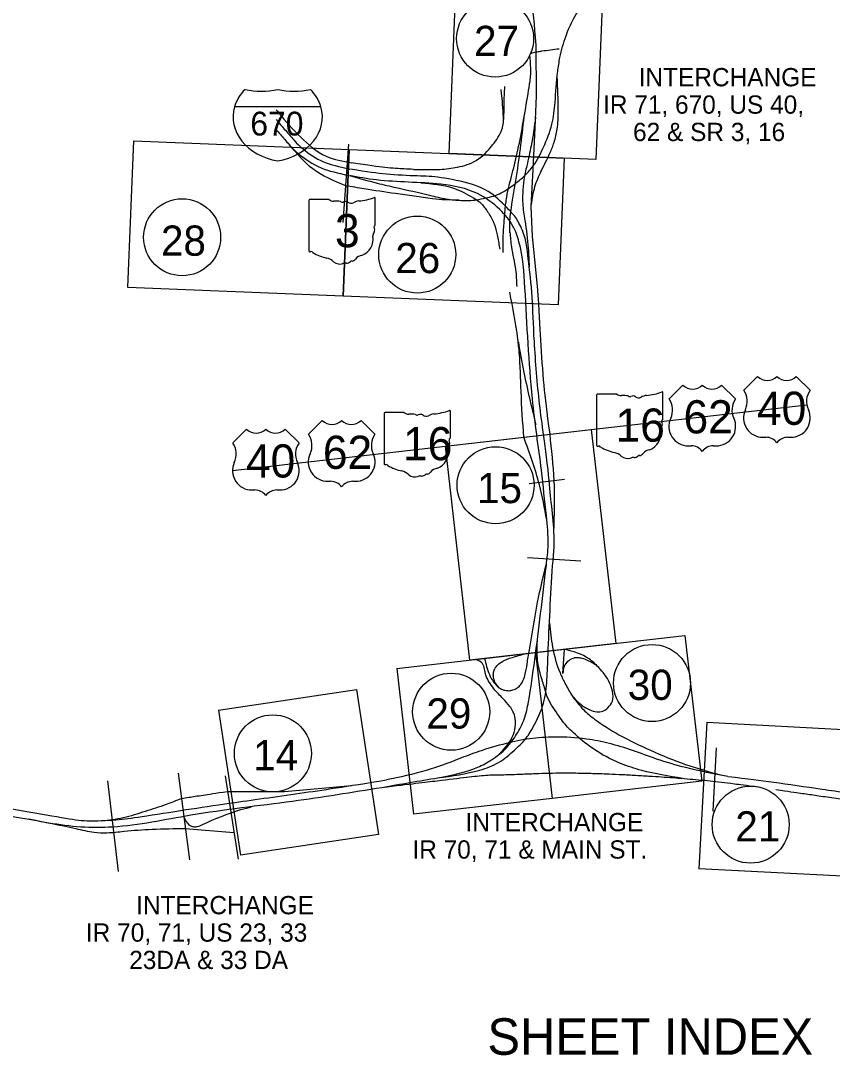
# Model space of a CAD drawing. Extents: x -13 to 322, y -402 to 112.
# Drawn here: x 3.22 to 7.61, y 67.48 to 73.08 of the extents above; entities that cross this region are included whole.
import ezdxf

# ---------------------------------------------------------------- set-up
doc = ezdxf.new("R2010")
doc.units = 0
for name, color, linetype in [('GM_X_Interstate_Shield', 7, 'Continuous'), ('GM_X_State_Shield', 7, 'Continuous'), ('GM_X_US_Shield', 7, 'Continuous'), ('SC_Scratch1', 7, 'Continuous'), ('SH_Data', 7, 'Continuous'), ('SH_Text', 7, 'Continuous')]:
    doc.layers.add(name, color=color, linetype=linetype)

msp = doc.modelspace()

# ---------------------------------------------------------------- linework, layer by layer
at = {"layer": 'GM_X_Interstate_Shield'}
msp.add_line((4.8438, 72.6183), (4.3763, 72.6183), dxfattribs=at)
msp.add_line((4.8438, 72.6183), (4.3763, 72.6183), dxfattribs=at)
for centre, start_param, end_param in [((4.6705, 72.5631), 2.47259, 2.911027), ((4.5218, 72.9442), 4.415841, 5.008937), ((4.6983, 72.9442), 4.415841, 5.008937), ((4.5496, 72.5631), 0.230566, 0.669003), ((4.6705, 72.5631), 2.911027, 4.511031), ((4.5496, 72.5631), 4.913747, 6.513751)]:
    msp.add_ellipse(centre, major_axis=(0.3022, 0), ratio=0.8, start_param=start_param, end_param=end_param, dxfattribs=at)
at = {"layer": 'GM_X_State_Shield'}
for p, q in [((4.7791, 72.1115), (4.7791, 71.8391)), ((4.8878, 72.1162), (4.7827, 72.1162)), ((5.1381, 71.9804), (5.1381, 72.1229)), ((5.1381, 71.9805), (5.1381, 71.9804)), ((6.3359, 71.059), (6.3359, 70.7865)), ((6.4445, 71.0637), (6.3394, 71.0637)), ((6.6948, 70.9279), (6.6948, 71.0704)), ((5.2942, 70.9635), (5.1891, 70.9635)), ((5.5445, 70.8277), (5.5445, 70.9702)), ((5.1855, 70.9588), (5.1855, 70.6863)), ((6.6948, 70.9279), (6.6948, 70.9279)), ((5.5445, 70.8277), (5.5445, 70.8277))]:
    msp.add_line(p, q, dxfattribs=at)
for centre, radius, start, end in [((4.7833, 72.1121), 0.00416, 98.1301, 188.1301), ((4.9128, 72.1478), 0.0403, 231.6195, 271.1119), ((4.9262, 71.9632), 0.1448, 80.4867, 94.9883), ((4.9591, 72.1135), 0.0116, 219.7921, 297.1024), ((4.9762, 72.082), 0.0242, 54.4667, 119.1411), ((5.0074, 72.1252), 0.0291, 233.8562, 294.8282), ((5.0588, 72.033), 0.0766, 97.3462, 120.7689), ((5.0102, 72.4876), 0.3807, 275.8445, 288.9065), ((5.1341, 72.1235), 0.004, 351.8621, 97.738), ((5.1372, 71.97), 0.00618, 107.944, 210.337), ((5.1338, 71.9799), 0.00428, 289.6038, 7.7341), ((5.0316, 71.9027), 0.0952, 292.3089, 8.9858), ((5.1524, 71.9208), 0.027, 136.8065, 186.9296), ((5.0978, 71.952), 0.0371, 340.033, 23.6496), ((4.7833, 71.8385), 0.0042, 171.9584, 258.3066), ((4.7839, 71.8663), 0.032, 267.339, 280.6039), ((4.7905, 71.8234), 0.0115, 29.7484, 93.2717), ((4.9362, 72.0681), 0.2749, 240.4129, 257.1985), ((4.8543, 71.7167), 0.086, 47.1842, 75.836), ((5.0717, 71.7626), 0.0521, 94.4031, 142.5768), ((4.9473, 71.822), 0.0546, 230.7004, 286.2918), ((4.9788, 71.7278), 0.0448, 85.6951, 111.2099), ((4.9828, 71.8016), 0.0291, 268.777, 315.5493), ((5.0091, 71.7752), 0.00819, 65.7517, 132.6484), ((5.0056, 71.8127), 0.0308, 282.8732, 323.2771), ((6.567, 71.4351), 0.3807, 275.8445, 288.9065), ((6.6909, 71.071), 0.004, 351.8621, 97.738), ((6.34, 71.0596), 0.00416, 98.1301, 188.1301), ((6.4696, 71.0953), 0.0403, 231.6195, 271.1119), ((6.4829, 70.9107), 0.1448, 80.4867, 94.9883), ((6.5158, 71.061), 0.0116, 219.7921, 297.1024), ((6.5329, 71.0295), 0.0242, 54.4667, 119.1411), ((6.5641, 71.0727), 0.0291, 233.8562, 294.8282), ((6.6155, 70.9805), 0.0766, 97.3462, 120.7689), ((5.1897, 70.9594), 0.00416, 98.1301, 188.1301), ((5.3192, 70.9951), 0.0403, 231.6195, 271.1119), ((5.4166, 71.3349), 0.3807, 275.8445, 288.9065), ((5.5405, 70.9708), 0.004, 351.8621, 97.738), ((5.3326, 70.8105), 0.1448, 80.4867, 94.9883), ((5.3655, 70.9608), 0.0116, 219.7921, 297.1024), ((5.3826, 70.9293), 0.0242, 54.4667, 119.1411), ((5.4138, 70.9725), 0.0291, 233.8562, 294.8282), ((5.4652, 70.8803), 0.0766, 97.3462, 120.7689), ((6.6939, 70.9174), 0.00618, 107.944, 210.337), ((6.6546, 70.8994), 0.0371, 340.033, 23.6496), ((6.6906, 70.9274), 0.00428, 289.6038, 7.7341), ((6.5883, 70.8501), 0.0952, 292.3089, 8.9858), ((6.7092, 70.8683), 0.027, 136.8065, 186.9296), ((5.5436, 70.8172), 0.00618, 107.944, 210.337), ((5.5042, 70.7992), 0.0371, 340.033, 23.6496), ((5.5402, 70.8271), 0.00428, 289.6038, 7.7341), ((5.438, 70.7499), 0.0952, 292.3089, 8.9858), ((5.5588, 70.7681), 0.027, 136.8065, 186.9296), ((6.34, 70.7859), 0.0042, 171.9584, 258.3066), ((6.3407, 70.8138), 0.032, 267.339, 280.6039), ((6.3472, 70.7708), 0.0115, 29.7484, 93.2717), ((6.493, 71.0156), 0.2749, 240.4129, 257.1985), ((6.411, 70.6641), 0.086, 47.1842, 75.836), ((6.5624, 70.7601), 0.0308, 282.8732, 323.2771), ((6.6284, 70.7101), 0.0521, 94.4031, 142.5768), ((5.1897, 70.6857), 0.0042, 171.9584, 258.3066), ((5.1903, 70.7136), 0.032, 267.339, 280.6039), ((5.1969, 70.6706), 0.0115, 29.7484, 93.2717), ((6.504, 70.7695), 0.0546, 230.7004, 286.2918), ((6.5356, 70.6753), 0.0448, 85.6951, 111.2099), ((6.5396, 70.7491), 0.0291, 268.777, 315.5493), ((6.5659, 70.7227), 0.00819, 65.7517, 132.6484), ((5.3426, 70.9154), 0.2749, 240.4129, 257.1985), ((5.2607, 70.5639), 0.086, 47.1842, 75.836), ((5.3537, 70.6693), 0.0546, 230.7004, 286.2918), ((5.3892, 70.6489), 0.0291, 268.777, 315.5493), ((5.4155, 70.6225), 0.00819, 65.7517, 132.6484), ((5.412, 70.6599), 0.0308, 282.8732, 323.2771), ((5.4781, 70.6098), 0.0521, 94.4031, 142.5768), ((5.3852, 70.5751), 0.0448, 85.6951, 111.2099)]:
    msp.add_arc(centre, radius, start, end, dxfattribs=at)
at = {"layer": 'GM_X_US_Shield'}
for p, q in [((7.2067, 71.1587), (7.1319, 71.0839)), ((7.4909, 71.0839), (7.4161, 71.1587)), ((6.803, 71.1124), (6.7282, 71.0376)), ((7.0871, 71.0376), (7.0124, 71.1124)), ((4.8514, 70.9204), (4.7766, 70.8457)), ((5.1356, 70.8457), (5.0608, 70.9204)), ((4.4412, 70.8734), (4.3664, 70.7987)), ((4.7253, 70.7987), (4.6506, 70.8734)), ((7.2366, 70.8296), (7.2516, 70.8296)), ((7.3712, 70.8296), (7.3862, 70.8296)), ((6.8329, 70.7834), (6.8478, 70.7834)), ((6.9675, 70.7834), (6.9824, 70.7834)), ((4.8813, 70.5914), (4.8963, 70.5914)), ((5.0159, 70.5914), (5.0309, 70.5914)), ((4.4711, 70.5444), (4.486, 70.5444)), ((4.6057, 70.5444), (4.6206, 70.5444))]:
    msp.add_line(p, q, dxfattribs=at)
for centre, radius, start, end in [((7.2591, 71.2121), 0.0748, 225.573, 314.427), ((7.3638, 71.2121), 0.0748, 225.573, 314.427), ((6.8553, 71.1658), 0.0748, 225.573, 314.427), ((6.96, 71.1658), 0.0748, 225.573, 314.427), ((7.0462, 71.0238), 0.1047, 334.5471, 35.0009), ((7.5766, 71.0238), 0.1047, 144.9991, 205.4529), ((6.6424, 70.9776), 0.1047, 334.5471, 35.0009), ((7.1729, 70.9776), 0.1047, 144.9991, 205.4529), ((7.2355, 70.9343), 0.1047, 154.8319, 270.6383), ((7.3874, 70.9343), 0.1047, 269.3617, 25.1681), ((4.9038, 70.9738), 0.0748, 225.573, 314.427), ((5.0085, 70.9738), 0.0748, 225.573, 314.427), ((6.8317, 70.8881), 0.1047, 154.8319, 270.6383), ((6.9836, 70.8881), 0.1047, 269.3617, 25.1681), ((4.4935, 70.9268), 0.0748, 225.573, 314.427), ((4.5982, 70.9268), 0.0748, 225.573, 314.427), ((4.2806, 70.7386), 0.1047, 334.5471, 35.0009), ((4.8111, 70.7386), 0.1047, 144.9991, 205.4529), ((4.6909, 70.7856), 0.1047, 334.5471, 35.0009), ((5.2213, 70.7856), 0.1047, 144.9991, 205.4529), ((7.2516, 70.7548), 0.0748, 36.8699, 90), ((7.3712, 70.7548), 0.0748, 90, 143.1301), ((4.8802, 70.6961), 0.1047, 154.8319, 270.6383), ((5.0321, 70.6961), 0.1047, 269.3617, 25.1681), ((6.8478, 70.7086), 0.0748, 36.8699, 90), ((6.9675, 70.7086), 0.0748, 90, 143.1301), ((4.4699, 70.6491), 0.1047, 154.8319, 270.6383), ((4.6218, 70.6491), 0.1047, 269.3617, 25.1681), ((4.8963, 70.5166), 0.0748, 36.8699, 90), ((5.0159, 70.5166), 0.0748, 90, 143.1301), ((4.486, 70.4696), 0.0748, 36.8699, 90), ((4.6057, 70.4696), 0.0748, 90, 143.1301)]:
    msp.add_arc(centre, radius, start, end, dxfattribs=at)
at = {"layer": 'SC_Scratch1'}
for p, q in [((4.9927, 72.4172), (4.9617, 71.9918)), ((5.9715, 70.5796), (6.1614, 70.6026)), ((5.962, 70.178), (6.2505, 70.1614)), ((6.9835, 69.1481), (6.9655, 68.8061)), ((4.0718, 69.0109), (4.1325, 68.5422)), ((3.6884, 68.9704), (3.746, 68.4786)), ((4.3255, 68.9978), (4.3956, 68.5458))]:
    msp.add_line(p, q, dxfattribs=at)
at = {"layer": 'SH_Data'}
for p, q in [((6.0114, 72.6785), (6.008, 72.9517)), ((6.0029, 72.5049), (6.0114, 72.6785)), ((5.9919, 72.2784), (6.0029, 72.5049)), ((5.9822, 72.0784), (5.9919, 72.2784)), ((5.9891, 71.9173), (5.9822, 72.0784)), ((6.0159, 71.6476), (5.9891, 71.9173)), ((4.3652, 70.6492), (7.4736, 71.0052)), ((5.6812, 69.6269), (6.1629, 69.682)), ((6.1531, 69.5515), (6.1629, 69.682)), ((4.6476, 68.9123), (5.0096, 68.9451)), ((4.3387, 68.9124), (4.6476, 68.9123)), ((4.1105, 68.7122), (4.3733, 68.6896))]:
    msp.add_line(p, q, dxfattribs=at)
for points in [[(6.008, 72.9517), (5.9996, 73.0713), (5.9862, 73.1903), (5.9331, 73.5852), (5.8824, 73.8595), (5.8496, 74.1336)], [(4.6013, 72.5504), (4.6147, 72.5344), (4.6283, 72.5185), (4.6877, 72.4504), (4.7345, 72.3955), (4.8585, 72.3096), (4.9386, 72.2972), (5.0003, 72.2815)], [(4.6013, 72.4959), (4.606, 72.4904), (4.6108, 72.4849), (4.6609, 72.4274), (4.7053, 72.3728), (4.8475, 72.2742), (4.9327, 72.2623), (4.9916, 72.2472)], [(5.3457, 72.2801), (5.3257, 72.281), (5.3059, 72.2818), (5.1937, 72.287), (5.1051, 72.3005), (5.0091, 72.3157)], [(6.073, 70.6552), (6.049, 70.8453), (6.0202, 71.0345), (5.9929, 71.4138), (5.9899, 71.6065), (5.9586, 71.8476), (5.9552, 71.8986), (5.9145, 71.9989), (5.8813, 72.0414), (5.7746, 72.1521), (5.6737, 72.2009), (5.478, 72.2413), (5.3801, 72.243), (5.1897, 72.2518), (5.0997, 72.2656), (5.0036, 72.2808)], [(6.0836, 70.846), (6.0668, 70.9734), (6.0509, 71.0999), (6.0319, 71.3634), (6.0271, 71.5075), (6.0159, 71.6476)], [(6.0966, 70.1345), (6.1062, 70.2154), (6.1091, 70.3124), (6.0892, 70.4835), (6.0821, 70.5683), (6.0731, 70.6544)], [(5.1737, 68.9343), (5.3294, 68.9531), (5.4851, 68.9719), (5.6408, 68.9907), (5.7364, 69.0022), (5.8329, 69.0026), (5.9291, 69.0063), (6.0036, 69.0091), (6.078, 69.0121), (6.1525, 69.0127), (6.1931, 69.0129), (6.2338, 69.0124), (6.2745, 69.0114), (6.3151, 69.0104), (6.3558, 69.0093), (6.3964, 69.0076), (6.4777, 69.0042), (6.559, 68.9997), (6.6403, 68.9946), (6.7022, 68.9907), (6.7641, 68.9861), (6.8259, 68.981), (6.8877, 68.9758), (6.9495, 68.9702), (7.0111, 68.9628), (7.0768, 68.9548), (7.1425, 68.9463), (7.2081, 68.9371)], [(2.1217, 68.7431), (2.1524, 68.7533), (2.1841, 68.7617), (2.3195, 68.7847), (2.4083, 68.7979), (2.5999, 68.8247), (2.6959, 68.8403), (2.9915, 68.8527), (3.1857, 68.8151), (3.4721, 68.767), (3.5635, 68.749), (3.7498, 68.7583), (3.8458, 68.7722), (4.1303, 68.8162), (4.3223, 68.8461), (4.7428, 68.9036), (4.9712, 68.9382), (5.1993, 68.9753)], [(7.0452, 68.9938), (7.1606, 68.9807), (7.2757, 68.9657), (7.5619, 68.9243), (7.7318, 68.8991), (7.903, 68.8824)], [(4.0894, 68.8749), (4.105, 68.8774), (4.1205, 68.8798), (4.2036, 68.8925), (4.2712, 68.9026), (4.3387, 68.9124)], [(7.3063, 68.9231), (7.3754, 68.9131), (7.4444, 68.9028), (7.5135, 68.8928), (7.6078, 68.8792), (7.7022, 68.8669), (7.7969, 68.857), (7.815, 68.8551), (7.8331, 68.8533), (7.8512, 68.8515)]]:
    msp.add_open_spline(points, degree=3, dxfattribs=at)
for points in [[(4.9981, 72.2459), (5.1483, 72.2055), (5.2518, 72.1811), (5.4323, 72.1404), (5.5235, 72.1195), (5.6034, 72.1121), (5.6861, 72.1153), (5.7355, 72.1253), (5.7778, 72.1357), (5.8594, 72.1765), (5.8968, 72.2042), (5.9464, 72.2456), (5.9929, 72.2989), (6.0481, 72.3994), (6.0943, 72.525), (6.1109, 72.6421), (6.1254, 72.809), (6.1376, 72.8857), (6.1702, 73.0026), (6.211, 73.0952), (6.2763, 73.1933), (6.3428, 73.2685), (6.3653, 73.2857), (6.4612, 73.3619), (6.542, 73.4064), (6.6444, 73.4447), (6.7391, 73.4623), (6.8117, 73.4683), (6.9653, 73.4683), (7.0726, 73.4713), (7.2097, 73.4784), (7.357, 73.494), (7.5219, 73.5113), (7.7497, 73.5556)], [(5.979, 72.908), (5.9941, 72.9119), (6.0093, 72.9154), (6.0322, 72.9197), (6.04, 72.9209), (6.0867, 72.9273), (6.1335, 72.9329)], [(5.8307, 71.8292), (5.8299, 71.9128), (5.8326, 71.9547), (5.8358, 71.9965), (5.8381, 72.0297), (5.8409, 72.0629), (5.8446, 72.096), (5.8495, 72.1289), (5.8631, 72.1933), (5.8791, 72.257), (5.8954, 72.3206), (5.91, 72.3846), (5.9389, 72.5362), (5.9651, 72.6888), (5.9757, 72.7581), (5.979, 72.7929), (5.9794, 72.8277), (5.9751, 72.8992)], [(5.9828, 72.0895), (6.0023, 72.1869), (6.0362, 72.2707), (6.0831, 72.367), (6.1058, 72.4252), (6.1226, 72.497), (6.1282, 72.5963), (6.1226, 72.7807)], [(5.3457, 72.2801), (5.4875, 72.2801), (5.5829, 72.2917), (5.6843, 72.3284), (5.7729, 72.4121), (5.823, 72.4964), (5.8344, 72.5725), (5.8387, 72.7194), (5.8395, 72.7293)], [(5.8322, 72.5483), (5.8228, 72.6802), (5.8193, 72.7129)], [(4.6013, 72.6031), (4.6152, 72.5858), (4.7329, 72.4554), (4.8727, 72.3505), (5.0091, 72.3157)], [(5.8667, 71.9364), (5.8669, 71.9987), (5.8716, 72.0497), (5.899, 72.22), (5.944, 72.5643)], [(6.0057, 72.5629), (5.9816, 72.4078), (5.9578, 72.2995), (5.9421, 72.2237), (5.936, 72.1509), (5.936, 72.0948), (5.9479, 72.0035), (5.9656, 71.8525), (5.9706, 71.7523)], [(4.9762, 72.1912), (4.7998, 72.2823), (4.6741, 72.4133)], [(6.038, 70.6508), (5.989, 71.0381), (5.948, 71.6379), (5.9158, 71.8882), (5.8832, 71.9727), (5.8122, 72.062), (5.6915, 72.1487), (5.4937, 72.199), (5.1441, 72.2228), (4.9981, 72.2459)], [(5.3853, 72.2063), (5.561, 72.1787), (5.6697, 72.1255), (5.7012, 72.1038), (5.7409, 72.0576), (5.7741, 72.0014), (5.7814, 71.9844), (5.7979, 71.9254), (5.811, 71.8557), (5.8128, 71.8475)], [(5.5897, 72.1126), (5.4477, 72.1203), (5.3484, 72.1346), (5.2474, 72.1487), (5.0775, 72.1744), (4.9762, 72.1912)], [(5.8664, 71.9395), (5.8749, 71.8599), (5.8972, 71.7377), (5.9034, 71.6464)], [(5.9419, 70.8298), (5.9272, 71.0771), (5.9175, 71.2886), (5.9097, 71.3616), (5.8661, 71.615)], [(5.9124, 71.3442), (5.9406, 71.1893), (6.0066, 70.899)], [(6.0662, 70.3829), (6.0265, 70.5721), (5.9419, 70.8298)], [(6.1048, 70.3186), (6.106, 70.5959), (6.0836, 70.846)], [(6.0638, 70.1363), (6.0737, 70.2486), (6.0638, 70.4038), (6.038, 70.6508)], [(5.1737, 68.9343), (5.4774, 68.9857), (5.7037, 69.0282), (5.8055, 69.0697), (5.8907, 69.1361), (5.9493, 69.1941), (5.9912, 69.259), (6.0484, 69.391), (6.067, 69.517), (6.0731, 69.6523), (6.0966, 70.1345)], [(5.4774, 68.9857), (5.6925, 69.0437), (5.7674, 69.084), (5.848, 69.149), (5.9031, 69.2226), (5.9441, 69.3039), (5.9668, 69.3972), (6.0009, 69.625), (6.033, 69.8762), (6.0638, 70.1363)], [(5.7294, 69.6324), (5.7555, 69.5453), (5.7784, 69.5047), (5.7988, 69.4811), (5.821, 69.4661), (5.8466, 69.4589), (5.8718, 69.4589), (5.8944, 69.4668), (5.916, 69.4814), (5.9323, 69.5027), (5.9479, 69.5409), (5.9599, 69.6037), (5.9648, 69.6401), (5.9721, 69.6798), (6.0168, 69.9366), (6.0645, 70.1452)], [(6.0815, 69.8241), (6.0973, 69.6941), (6.1377, 69.5546), (6.1636, 69.5001), (6.2002, 69.4363), (6.2658, 69.3546), (6.324, 69.3045), (6.4564, 69.2197), (6.6278, 69.1356), (6.8176, 69.0588), (7.0045, 69.0023)], [(6.8007, 68.9828), (6.5797, 69.0263), (6.4655, 69.0642), (6.3129, 69.1462), (6.2086, 69.2315), (6.1521, 69.2922), (6.1247, 69.3316), (6.0666, 69.4308), (6.0519, 69.4806), (6.0295, 69.5544), (6.0149, 69.6458), (6.0156, 69.7371)], [(6.2064, 69.427), (6.2585, 69.3775), (6.2995, 69.3546), (6.3363, 69.3438), (6.3699, 69.347), (6.3969, 69.3654), (6.4212, 69.4003), (6.4212, 69.4553), (6.406, 69.5012), (6.3807, 69.5439), (6.3473, 69.5828), (6.2949, 69.6307), (6.1629, 69.682)], [(5.8061, 69.1116), (5.8777, 69.2031), (5.8954, 69.2615), (5.8954, 69.3067), (5.8832, 69.3453), (5.866, 69.3727), (5.8299, 69.4146), (5.7801, 69.4679), (5.7548, 69.5046), (5.7365, 69.5413), (5.7174, 69.6049), (5.6812, 69.6269)], [(5.8091, 69.4728), (5.7856, 69.5046), (5.7776, 69.5302), (5.7776, 69.5522), (5.7842, 69.5747), (5.801, 69.5985), (5.8275, 69.6171), (5.8782, 69.6374), (5.9472, 69.6573)], [(6.2141, 69.6345), (6.1847, 69.6199), (6.1599, 69.5882), (6.1531, 69.5515)], [(6.3388, 69.5923), (6.2907, 69.6199), (6.2583, 69.6321), (6.2363, 69.6357), (6.2193, 69.6357), (6.2141, 69.6345)], [(7.0452, 68.9938), (6.8181, 69.0413), (6.66, 69.0879), (6.53, 69.1344), (6.4048, 69.1721), (6.2812, 69.1962), (6.1095, 69.2066), (5.9731, 69.1978), (5.8463, 69.1721), (5.6978, 69.1288), (5.5911, 69.0887), (5.4129, 69.0253), (5.1993, 68.9753)], [(0.4227, 68.1866), (0.4736, 68.1951), (0.8015, 68.2291), (1.1958, 68.2632), (1.5004, 68.403), (2.0434, 68.6736), (2.2244, 68.7327), (2.5111, 68.7757), (2.7075, 68.8021), (2.9708, 68.8021), (3.1973, 68.7734), (3.5452, 68.7216), (3.7165, 68.7216), (4.1393, 68.785), (4.69, 68.8605), (5.1737, 68.9343)], [(3.6575, 68.7537), (3.7743, 68.7713), (3.895, 68.8062), (4.0074, 68.8433), (4.0894, 68.8749)], [(4.1028, 68.7717), (4.1204, 68.7423), (4.1358, 68.728), (4.1532, 68.7219), (4.1739, 68.7219), (4.2033, 68.7329), (4.4107, 68.8139), (4.4703, 68.8304)], [(3.2609, 68.7643), (3.5168, 68.7115), (3.6165, 68.6922), (3.686, 68.689), (3.7788, 68.6968), (3.9305, 68.7079), (4.1105, 68.7122)]]:
    msp.add_spline(points, degree=3, dxfattribs=at)
at = {"layer": 'SH_Text'}
for p, q in [((5.5388, 72.3659), (5.5855, 73.5304)), ((6.379, 73.4985), (6.3323, 72.3341)), ((3.7996, 71.6409), (3.8315, 72.4344)), ((3.8315, 72.4344), (4.996, 72.3877)), ((4.9641, 71.5942), (4.996, 72.3877)), ((4.996, 72.3877), (4.9641, 71.5942)), ((4.996, 72.3877), (6.1605, 72.3409)), ((6.3323, 72.3341), (5.5388, 72.3659)), ((6.1605, 72.3409), (6.1286, 71.5474)), ((4.9641, 71.5942), (3.7996, 71.6409)), ((6.1286, 71.5474), (4.9641, 71.5942)), ((5.5176, 70.7812), (6.3066, 70.8716)), ((6.3066, 70.8716), (6.4392, 69.7137)), ((5.6503, 69.6233), (5.5176, 70.7812)), ((6.0051, 69.664), (6.8141, 69.7566)), ((6.8141, 69.7566), (6.9045, 68.9676)), ((6.4392, 69.7137), (5.6503, 69.6233)), ((5.2543, 69.578), (6.0051, 69.664)), ((6.0051, 69.664), (6.0955, 68.875)), ((5.2546, 69.578), (5.345, 68.789)), ((4.2893, 69.3525), (5.0366, 69.4652)), ((5.0366, 69.4652), (5.1551, 68.6799)), ((4.2897, 69.3525), (4.4082, 68.5673)), ((6.9314, 69.2874), (6.8895, 68.4943)), ((6.9314, 69.2874), (7.7446, 69.2444)), ((6.9045, 68.9676), (6.0955, 68.875)), ((6.0955, 68.875), (5.345, 68.789)), ((5.1551, 68.6799), (4.4082, 68.5673)), ((7.7027, 68.4514), (6.8895, 68.4943))]:
    msp.add_line(p, q, dxfattribs=at)
for centre in [(5.7866, 72.9879), (4.0929, 71.9123), (5.3653, 71.8187), (5.7891, 70.5702), (6.6356, 69.4993), (5.5487, 69.3441), (4.5838, 69.1186), (7.1696, 68.7329)]:
    msp.add_circle(centre, 0.2084, dxfattribs=at)

# ---------------------------------------------------------------- texts
at = {"layer": 'GM_X_Interstate_Shield'}
msp.add_text('670', height=0.12892, dxfattribs=at).set_placement((4.4618, 72.4632))
at = {"layer": 'GM_X_State_Shield'}
for s, height, p in [('3', 0.1795, (4.9199, 71.8583)), ('16', 0.17948, (6.4382, 70.8058)), ('16', 0.17948, (5.2879, 70.7055))]:
    msp.add_text(s, height=height, dxfattribs=at).set_placement(p)
at = {"layer": 'GM_X_US_Shield'}
for s, p in [('40', (7.2036, 70.8969)), ('62', (6.8061, 70.8507)), ('40', (4.438, 70.6117)), ('62', (4.8545, 70.6587))]:
    msp.add_text(s, height=0.17948, dxfattribs=at).set_placement(p)
at = {"layer": 'SH_Text'}
for s, height, p in [('27', 0.16356, (5.6726, 72.8934)), ('INTERCHANGE', 0.098862, (6.5634, 72.7296)), ('IR 71, 670, US 40,', 0.098862, (6.3707, 72.5813)), ('62 & SR 3, 16', 0.098862, (6.533, 72.4331)), ('28', 0.16356, (3.9783, 71.8124)), ('26', 0.16356, (5.2462, 71.7181)), ('15', 0.16356, (5.6886, 70.4731)), ('30', 0.16356, (6.5043, 69.408)), ('29', 0.16356, (5.4148, 69.2528)), ('14', 0.16356, (4.4776, 69.0273)), ('INTERCHANGE', 0.098862, (5.6261, 68.6971)), ('21', 0.16356, (7.0864, 68.6416)), ('IR 70, 71 & MAIN ST.', 0.098862, (5.3389, 68.5489)), ('INTERCHANGE', 0.098862, (3.8438, 68.2476)), ('IR 70, 71, US 23, 33', 0.098862, (3.5721, 68.0993)), ('23DA & 33 DA', 0.098862, (3.8064, 67.951)), ('SHEET INDEX', 0.197725, (5.7451, 67.4869))]:
    msp.add_text(s, height=height, dxfattribs=at).set_placement(p)

doc.saveas('drawing.dxf')
